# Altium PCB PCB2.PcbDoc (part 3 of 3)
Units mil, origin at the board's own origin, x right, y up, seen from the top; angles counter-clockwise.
Board outline 10275.59 x 4173.23 mil, 2 copper layers (Top Layer, Bottom Layer); 158 components, 159 nets, 776 pads, 338 vias.
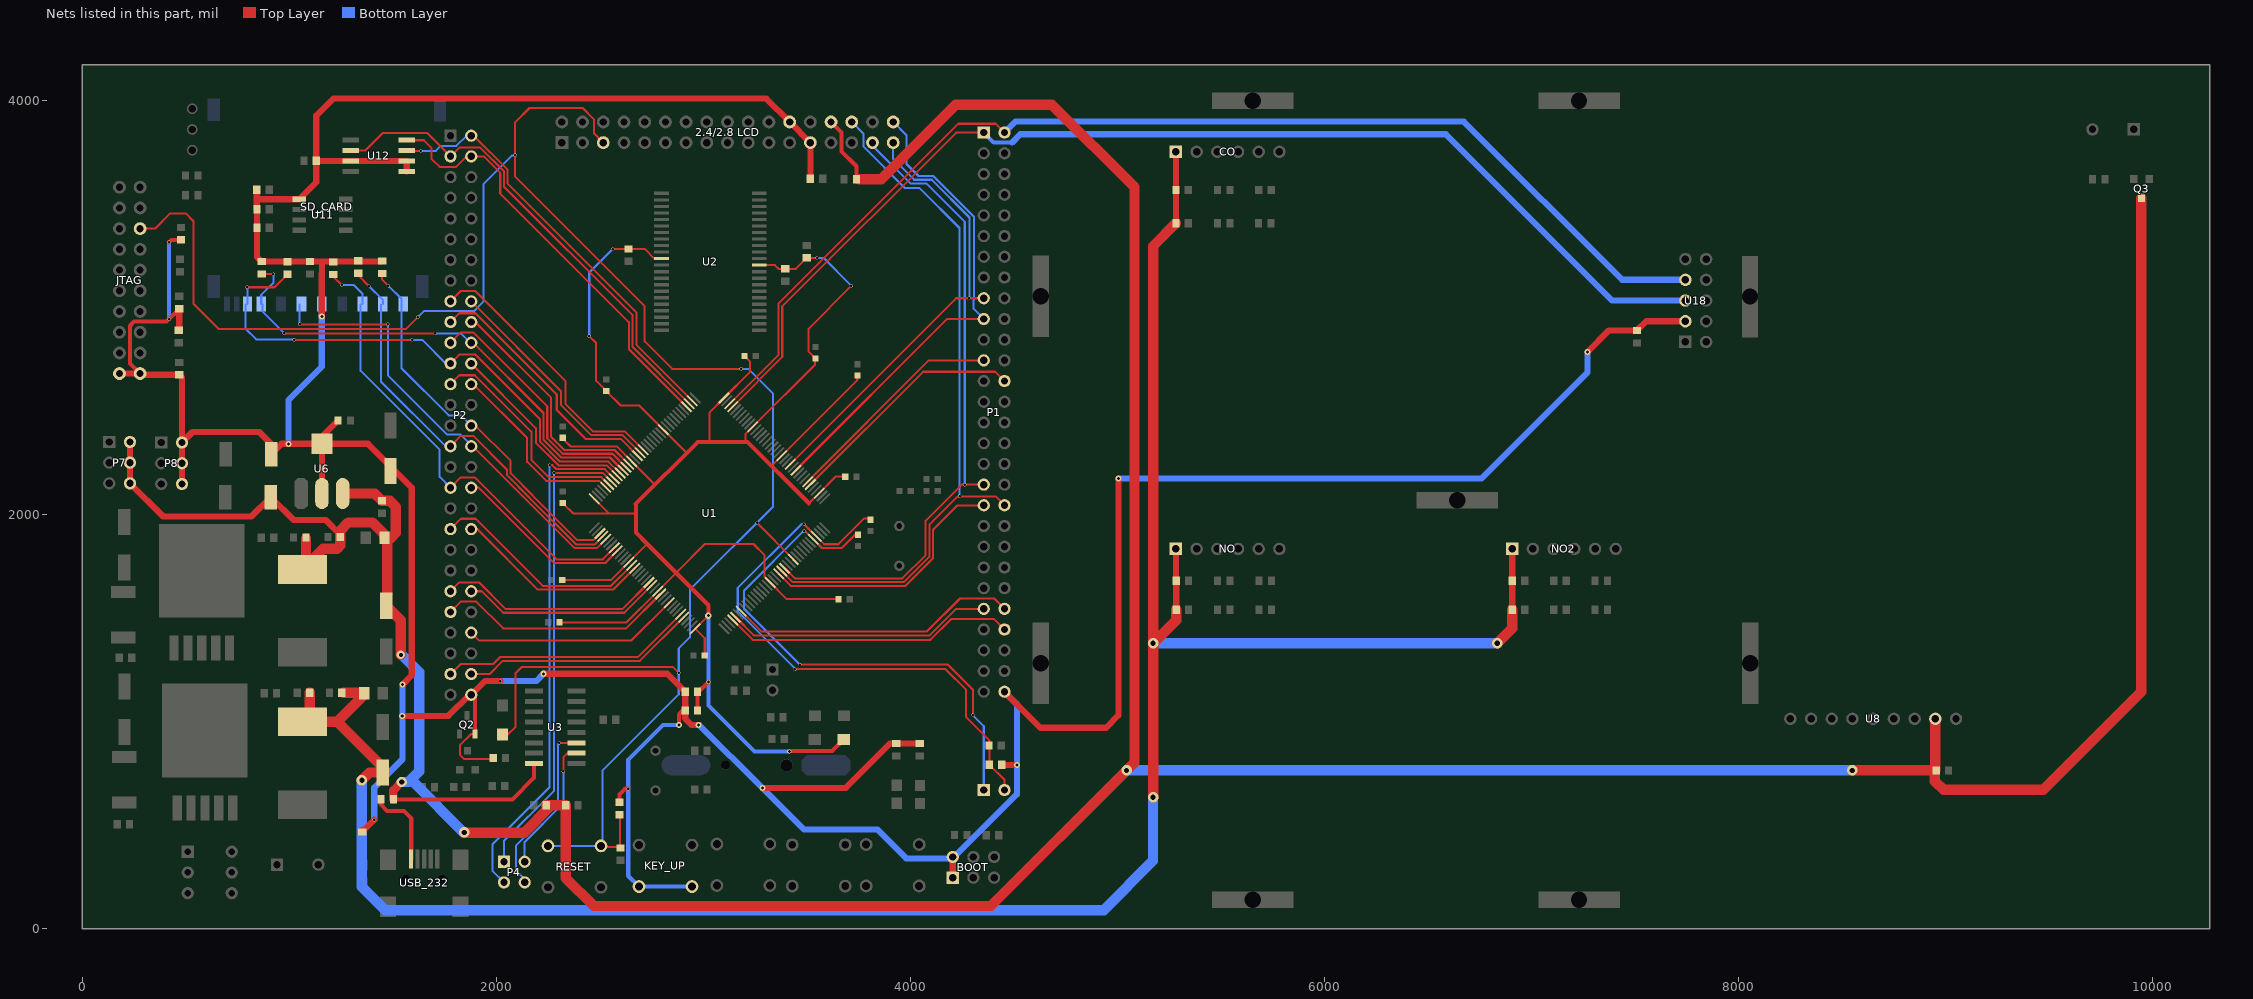
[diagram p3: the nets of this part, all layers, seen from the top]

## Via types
v1: diameter 16, hole 12, Top Layer to Bottom Layer, 183 vias
v2: diameter 60, hole 36, Top Layer to Bottom Layer, 50 vias
v3: diameter 27.56, hole 27.56, Top Layer to Bottom Layer, 32 vias
v4: diameter 30, hole 15, Top Layer to Bottom Layer, 27 vias
v5: diameter 50, hole 25, Top Layer to Bottom Layer, 19 vias
v6: diameter 125.98, hole 125.98, Top Layer to Bottom Layer, 16 vias
v7: diameter 20, hole 15, Top Layer to Bottom Layer, 4 vias
v8: diameter 196.85, hole 118.11, Top Layer to Bottom Layer, 4 vias
v9: diameter 30, hole 20, Top Layer to Bottom Layer, 1 vias
v10: diameter 40, hole 20, Top Layer to Bottom Layer, 1 vias
v11: diameter 50, hole 28, Top Layer to Bottom Layer, 1 vias

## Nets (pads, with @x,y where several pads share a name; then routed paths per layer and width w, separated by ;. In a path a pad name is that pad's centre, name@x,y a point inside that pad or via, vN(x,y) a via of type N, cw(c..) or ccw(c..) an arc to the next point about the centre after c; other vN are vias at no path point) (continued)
PA6: P1.26 U1.42 | length 1181.3
  Top Layer w10: U1.42@3517.19,2145.31 4061.48,2689.61 4409.37,2689.61 P1.26@4454.37,2644.61
PA7: P1.23 U1.43 | length 1093.6
  Top Layer w10: U1.43@3503.27,2159.23 4088.64,2744.61 P1.23@4354.37,2744.61
PA8: P2.24 U1.100 | length 971.4
  Top Layer w10: P2.24@1879.37,2729.61 2191.37,2417.61 2191.37,2346.83 2300.6,2237.61 2534.05,2237.61 U1.100@2584.59,2187.07
PA9: P4.3 U1.101 | length 2493.3
  Top Layer w10: v1(2257.37,2238.61) 2271.37,2238.61 2287.37,2222.61 2288.07,2222.61 2291.07,2219.61 2524.17,2219.61 U1.101@2570.9,2172.88
  Bottom Layer w10: P4.3@2037.37,223.61 1981.37,279.61 1981.37,406.61 2257.37,682.61 v1(2257.37,2238.61)
PA10: P4.1 U1.102 | length 2273.5
  Top Layer w10: v1(2279.37,2201.61) 2514.34,2201.61 U1.102@2556.98,2158.96
  Bottom Layer w10: P4.1@2037.37,323.61 2037.37,424.61 2279.37,666.61 v1(2279.37,2201.61)
PA11: P2.25 U1.103 | length 1079.4
  Top Layer w10: P2.25@1779.37,2629.61 1822.37,2672.61 1896.51,2672.61 2169.37,2399.75 2169.37,2264.61 2253.37,2180.61 2459.22,2180.61 2459.49,2180.87 2507.23,2180.87 U1.103@2543.06,2145.04
PA12: P2.26 U1.104 | length 923.8
  Top Layer w10: P2.26@1879.37,2629.61 1882.37,2626.61 1892.37,2626.61 2149.37,2369.61 2149.37,2254.61 2241.37,2162.61 2466.68,2162.61 2466.94,2162.87 2497.39,2162.87 U1.104@2529.14,2131.12
PB1: "2.4/2.8 LCD.34" P1.19 U1.47 | length 2384.3
  Top Layer w10: U1.47@3447.59,2214.91 4177.29,2944.61 P1.19@4354.37,2944.61
  Bottom Layer w10: 3917,3896 3981,3832 3981,3692.98 4039.37,3634.61 4110.83,3634.61 4306.37,3439.06 4306.37,3035.91 4305.37,3034.91 4305.37,2993.61 P1.19@4354.37,2944.61
PB5: P2.50 U1.135 | length 1046.5
  Top Layer w10: P2.50@1879.37,1429.61 1916.37,1392.61 2653.13,1392.61 U1.135@2835.14,1574.61
PB8: P2.53 U1.139 | length 1231.3
  Top Layer w10: P2.53@1779.37,1229.61 1827.37,1277.61 1984.37,1277.61 2018.37,1311.61 2683.48,1311.61 U1.139@2890.81,1518.94
PB9: P2.54 U1.140 | length 1139.4
  Top Layer w10: P2.54@1879.37,1229.61 1967.37,1229.61 2031.37,1293.61 2693.32,1293.61 U1.140@2904.73,1505.02
PB10: P1.1 U1.69 U18.5 | length 5661.6
  Top Layer w10: U1.69@3141.36,2521.13 3381.37,2761.14 3381.37,3005 4220.98,3844.61 P1.1@4354.37,3844.61
  Bottom Layer w10: 4530.91,3836.61 4534.91,3836.61
  Bottom Layer w20: P1.1@4354.37,3844.61 4402.37,3796.61 4490.91,3796.61
  Bottom Layer w30: 4490.91,3796.61 4530.91,3836.61 ; 4534.91,3836.61 6585.91,3836.61 7389.06,3033.46 U18.5@7742.78,3033.46
PB11: P1.2 U1.70 U18.7 | length 5676.5
  Top Layer w10: U1.70@3127.44,2535.05 3362.37,2769.98 3362.37,3017.61 4231.9,3887.13 4411.84,3887.13 P1.2@4454.37,3844.61
  Bottom Layer w30: P1.2@4454.37,3844.61 4507.37,3897.61 6672.91,3897.61 7437.06,3133.46 U18.7@7742.78,3133.46
PB13: P2.2 U1.74 U12.7 | length 2046.1
  Top Layer w10: U12.7@1570.37,3755.61 v1(1635.37,3755.61) ; P2.2@1879.37,3829.61 1890.28,3829.61 2055.37,3664.52 2055.37,3597.61 2676.37,2976.61 2676.37,2819.06 U1.74@2946.72,2548.7
  Bottom Layer w10: v1@1635.37,3756.61 1708.37,3756.61 1732.37,3780.61 1807.81,3780.61 P2.2@1856.81,3829.61
PB14: P2.3 U1.75 U12.2 | length 2379.5
  Top Layer w10: U12.2@1298.37,3757.54 1366.31,3757.54 1451.37,3842.61 1666.37,3842.61 P2.3@1779.37,3729.61 1821.9,3772.13 1922.3,3772.13 2037.37,3657.06 2037.37,3582.89 2658.37,2961.89 2658.37,2809.22 U1.75@2932.8,2534.78
PB15: P2.4 U1.76 U12.8 | length 2091.1
  Top Layer w10: U12.8@1568.37,3807.61 1650.37,3807.61 1688.37,3769.61 1688.37,3716.61 1726.37,3678.61 1806.37,3678.61 1857.37,3729.61 P2.4@1879.37,3729.61 1939.37,3729.61 2019.37,3649.61 2019.37,3549.61 2640.37,2928.61 2640.37,2799.38 U1.76@2918.89,2520.87
PC6: P2.20 U1.96 | length 1156.1
  Top Layer w10: P2.20@1879.37,2929.61 1899.37,2929.61 2265.37,2563.61 2265.37,2374.66 2328.42,2311.61 2571.4,2311.61 U1.96@2640.26,2242.74
PC7: P2.21 U1.97 | length 1227.8
  Top Layer w10: P2.21@1779.37,2829.61 1829.37,2879.61 1889.51,2879.61 2246.37,2522.75 2246.37,2368.2 2320.97,2293.61 2561.56,2293.61 U1.97@2626.34,2228.83
PC8: P2.22 R21.2 SD_CARD.7 U1.98 | length 2391.1
  Top Layer w10: R21.2@867.37,3161.61 v1@923.37,3161.61 ; v1(976.8,2874.61) v1(1706.37,2874.61) ; P2.22@1879.37,2829.61 1889.37,2829.61 2228.37,2490.61 2228.37,2360.75 2313.51,2275.61 2549.34,2275.61 2610.04,2214.91 U1.98@2612.42,2214.91
  Bottom Layer w10: SD_CARD.7@865.44,3016.97 865.44,3060.68 924.37,3119.61 v1(924.37,3160.61) ; SD_CARD.7@870.37,3013.61 870.37,2981.04 v1(976.8,2874.61) ; v1@1707.37,2874.61 1829.37,2874.61 1874.37,2829.61 P2.22@1879.37,2829.61
PC9: P2.23 R22.2 SD_CARD.8 U1.99 | length 2616
  Top Layer w10: v1(798.37,3097.61) 929.37,3097.61 R22.2@992.37,3160.61 ; v1(1025.37,2843.61) v1(1593.37,2843.61) ; P2.23@1779.37,2729.61 1821.9,2772.13 1899.84,2772.13 2210.37,2461.61 2210.37,2353.29 2308.05,2255.61 2541.5,2255.61 2596.12,2200.99 U1.99@2598.51,2200.99
  Bottom Layer w10: SD_CARD.8@789.37,3014.61 789.37,2896.61 840.37,2845.61 v1@1023.37,2845.61 ; SD_CARD.8@798.37,3016.61 v1(798.37,3097.61) ; v1@1022.72,2846.26 v1@1023.37,2845.61 ; v1(1025.37,2843.61) v1@1023.37,2845.61 ; v1(1593.37,2843.61) 1642.37,2843.61 1756.37,2729.61 P2.23@1779.37,2729.61
PC10: P2.30 R18.1 SD_CARD.9 U1.111 | length 1848.4
  Top Layer w10: R18.1@1449.37,3164.61 1449.37,3134.61 v1(1479.37,3104.61) ; P2.30@1879.37,2429.61 1899.37,2429.61 2069.37,2259.61 2069.37,2198.69 2178.37,2089.69 2178.37,2089 2390.71,1876.66 2469.05,1876.66 U1.111@2501.07,1908.68
  Bottom Layer w10: v1(1479.37,3104.61) 1542.46,3041.51 1542.46,2706.37 1770.23,2478.61 1830.37,2478.61 P2.30@1879.37,2429.61
PC11: P2.31 R23.2 SD_CARD.1 U1.112 | length 2032.1
  Top Layer w10: R23.2@1333.37,3155.61 v1(1385.37,3103.61) ; P2.31@1779.37,2329.61 1829.37,2379.61 1889.51,2379.61 2051.37,2217.75 2051.37,2191.24 2160.37,2082.24 2160.37,2081.54 2386.3,1855.61 2475.84,1855.61 U1.112@2514.99,1894.76
  Bottom Layer w10: v1(1385.37,3103.61) 1452.37,3036.61 SD_CARD.1@1452.37,3016.61 ; SD_CARD.1@1443.37,3014.61 1443.37,2641.61 1755.37,2329.61 P2.31@1779.37,2329.61
PC12: P2.32 SD_CARD.5 U1.113 | length 2184.1
  Top Layer w10: v1(1050.34,2918.61) v1@1477.37,2918.61 ; P2.32@1879.37,2329.61 1887.55,2329.61 2142.37,2074.78 2142.37,2074.08 2378.85,1837.61 2485.67,1837.61 U1.113@2528.91,1880.84
  Bottom Layer w10: v1(1050.34,2918.61) SD_CARD.5@1050.34,3014.97 ; v1(1476.37,2918.61) 1476.37,2672.46 1761.75,2387.08 1826.9,2387.08 P2.32@1879.37,2334.61
PC13: P1.48 U1.7 | length 1398.1
  Top Layer w10: U1.7@3183.12,1532.86 3280.37,1435.61 4080.37,1435.61 4239.37,1594.61 4404.37,1594.61 P1.48@4454.37,1544.61
PD2: P2.35 R20.2 SD_CARD.2 U1.116 | length 2299.7
  Top Layer w10: R20.2@1213.37,3159.61 1213.37,3148.61 v1(1253.37,3108.61) ; P2.35@1779.37,2129.61 1829.37,2179.61 1896.37,2179.61 2292.37,1783.61 2515.19,1783.61 U1.116@2570.67,1839.08
  Bottom Layer w10: v1(1253.37,3108.61) 1312.37,3108.61 1354.37,3066.61 SD_CARD.2@1354.37,3016.61 ; SD_CARD.2@1345.37,3014.61 1345.37,2693.61 1726.37,2312.61 1726.37,2182.61 P2.35@1779.37,2129.61
PD3: P2.36 U1.117 | length 880.7
  Top Layer w10: P2.36@1879.37,2129.61 1915.37,2129.61 2279.37,1765.61 2525.03,1765.61 U1.117@2584.59,1825.16
PD6: P2.39 U1.122 | length 1071.2
  Top Layer w10: P2.39@1779.37,1929.61 1829.37,1979.61 1900.37,1979.61 2224.43,1655.54 2554.16,1655.54 U1.122@2654.18,1755.57
PD7: P2.40 U1.123 | length 952.8
  Top Layer w10: P2.40@1879.37,1929.61 1909.37,1929.61 2201.43,1637.54 2564,1637.54 U1.123@2668.1,1741.65
PE5: P1.50 U1.4 | length 1415.1
  Top Layer w10: U1.4@3141.36,1491.1 3237.85,1394.61 4096.37,1394.61 4196.37,1494.61 4404.37,1494.61 P1.50@4454.37,1444.61
PE6: P1.47 U1.5 | length 1288.7
  Top Layer w10: U1.5@3155.28,1505.02 3243.69,1416.61 4092.91,1416.61 4220.91,1544.61 P1.47@4354.37,1544.61
PF8: P1.37 U1.20 | length 1256.4
  Top Layer w10: U1.20@3364.07,1713.81 3422.27,1655.61 3706.51,1655.61 3706.57,1655.67 3777.17,1655.67 3777.23,1655.61 3976.28,1655.61 4109.37,1788.69 4109.37,1926.61 4227.37,2044.61 P1.37@4354.37,2044.61
PF9: "2.4/2.8 LCD.30" P1.38 U1.21 | length 3443.7
  Top Layer w10: U1.21@3377.99,1727.73 3432.11,1673.61 3699.05,1673.61 3699.12,1673.67 3784.62,1673.67 3784.69,1673.61 3968.83,1673.61 4091.37,1796.15 4091.37,1950.61 4228.37,2087.61 4411.37,2087.61 P1.38@4454.37,2044.61
  Bottom Layer w10: 3717,3896 3773,3840 3773,3777.78 3974.17,3576.61 4044.37,3576.61 4237.37,3383.61 v1(4237.37,2087.61)
PF10: "2.4/2.8 LCD.31" P1.35 U1.22 | length 3149.9
  Top Layer w10: U1.22@3391.91,1741.65 3441.95,1691.61 3691.6,1691.61 3691.66,1691.67 3792.08,1691.67 3792.14,1691.61 3961.37,1691.61 4073.37,1803.61 4073.37,1970.61 4247.37,2144.61 P1.35@4354.37,2144.61
  Bottom Layer w10: 3817,3796 3817,3781.61 4001,3597.61 4078.37,3597.61 4262.37,3413.61 v1(4262.37,2144.61)
PF11: "2.4/2.8 LCD.33" P1.17 U1.49 | length 2219.7
  Top Layer w10: U1.49@3419.75,2242.74 4221.61,3044.61 P1.17@4354.37,3044.61
  Bottom Layer w10: 3917,3796 3917,3717.61 4018,3616.61 4103.37,3616.61 4285.37,3434.61 v1(4285.37,3045.61)
PG6: P2.17 U1.91 | length 1334.1
  Top Layer w10: P2.17@1779.37,3029.61 1829.37,3079.61 1899.37,3079.61 2335.37,2643.61 2335.37,2533.06 2466.83,2401.61 2620.56,2401.61 U1.91@2710.09,2312.07
PG7: P2.18 U1.92 | length 1158.1
  Top Layer w10: P2.18@1879.37,3029.61 2312.37,2596.61 2312.37,2530.61 2459.37,2383.61 2610.76,2383.61 U1.92@2695.94,2298.42
PG8: P2.19 U1.93 | length 1249.4
  Top Layer w10: P2.19@1779.37,2929.61 1821.9,2972.13 1899.84,2972.13 2292.37,2579.61 2292.37,2504.61 2431.37,2365.61 2600.89,2365.61 U1.93@2682.26,2284.24
PG13: P2.45 U1.128 | length 1082.4
  Top Layer w10: P2.45@1779.37,1629.61 1821.9,1672.13 1916.84,1672.13 2045.37,1543.61 2609.26,1543.61 U1.128@2737.7,1672.05
PG14: P2.46 U1.129 | length 970.2
  Top Layer w10: P2.46@1879.37,1629.61 1929.37,1629.61 2033.37,1525.61 2619.09,1525.61 U1.129@2751.62,1658.13
PG15: P2.47 U1.132 | length 1156.8
  Top Layer w10: P2.47@1779.37,1529.61 1829.37,1579.61 1904.37,1579.61 2033.37,1450.61 2627.61,1450.61 U1.132@2793.38,1616.37
RESET: "2.4/2.8 LCD.5" C12.2 D3.1 JTAG.15 R3.1 RESET.1 U1.25 | length 10024.3
  Top Layer w10: JTAG.15@280.37,3380.61 352.37,3380.61 426.37,3454.61 500.37,3454.61 538.37,3416.61 538.37,3018.61 661.37,2895.61 1563.37,2895.61 v1(1620.37,2952.61) ; D3.1@2030.37,937.61 2056.37,937.61 2092.37,973.61 2092.37,1232.61 2124.37,1264.61 2853.37,1264.61 v1(2881.37,1236.61) ; RESET.1@2512.28,414.61 2532.28,394.61 2597.37,394.61 2597.37,548.61 R3.1@2595.37,550.61 ; 2517,3796 2473,3840 2473,3907 2417,3963 2160.76,3963 2091.37,3893.61 v1(2091.37,3734.61) 2091.37,3631.61 2716.37,3006.61 2716.37,2836.61 2849.37,2703.61 v1(3183.37,2703.61) ; v1(3259.37,1959.61) U1.25@3433.67,1783.4
  Bottom Layer w10: v1(1620.37,2952.61) 1650.37,2982.61 1892.51,2982.61 1939.37,3029.46 1939.37,3596.61 2077.37,3734.61 v1(2091.37,3734.61) ; RESET.1@2256.37,412.61 2268.98,400 2512.28,400 2512.28,762.51 2881.37,1131.61 2881.37,1353.61 2935.37,1407.61 2935.37,1636.61 3337.37,2038.61 3337.37,2582.61 3216.37,2703.61 v1(3183.37,2703.61)
RXD: P4.4 U3.3 | length 861.2
  Top Layer w10: v1(2305.37,897.61) U3.3@2387.73,897.61
  Bottom Layer w10: P4.4@2137.37,223.61 2137.37,238.55 2094.84,281.08 2094.84,401.53 2298.37,605.06 2298.37,890.61 v1(2305.37,897.61)
TXD: P4.2 U3.2 | length 655.7
  Top Layer w10: v1(2324.37,759.61) 2324.37,828.61 2343.37,847.61 U3.2@2387.73,847.61
  Bottom Layer w10: P4.2@2137.37,323.61 2137.37,418.61 2324.37,605.61 v1@2324.37,761.61
VCC3.3: "2.4/2.8 LCD.24" "2.4/2.8 LCD.25" BOOT.1 BOOT.2 C3.1 C30.2 C32.1 C33.1 C34.2 C49.1 C50.1 D7.2 JTAG.1 JTAG.2 KEY_UP.1 P1.56 P2.56 P8.2 P8.4 P8.6 Q2.2 R3.2 R4.2 R5.1 R6.1 R7.1 R8.1 R9.1 R10.1 R18.2 R19.1 R20.1 R21.1 R22.1 R23.1 R24.1 R25.1 R26.1 R28.1 R29.1 SD_CARD.4 U6.2 U6.4 U11.5 U12.3 U12.5 U12.6 U18.3 | length 23111
  Top Layer w10: Q2.2@1896.77,940.31 1879.08,940.31 1824.37,885.61 1824.37,840.61 1846.37,818.61 R19.1@1985.37,818.61
  Top Layer w20: JTAG.1@280.37,2680.61 231.37,2729.61 231.37,2911.61 251.37,2931.61 407.37,2931.61 R7.1@469.37,2993.61 ; v1(420.37,3314.61) 432.37,3326.61 R10.1@477.37,3326.61 ; P2.56@1879.37,1129.61 1896.77,1112.2 Q2.2@1896.77,940.31 ; R3.2@2595.37,610.61 2595.37,648.61 2623.37,676.61 v1(2637.37,676.61) ; v4(2882.37,983.61) 2882.37,1035.74 R9.1@2903.8,1057.17
  Top Layer w30: JTAG.2@180.37,2680.61 JTAG.1@280.37,2680.61 ; JTAG.1@286.37,2674.61 R5.1@469.37,2674.61 482.37,2661.61 P8.2@482.37,2347.61 ; R6.1@469.37,2892.61 R7.1@469.37,2993.61 ; P8.6@482.37,2147.61 P8.4@482.37,2247.61 P8.2@482.37,2347.61 ; C32.1@843.37,3568.61 843.37,3475.61 R28.1@844.37,3474.61 ; R22.1@991.37,3221.61 R21.1@867.37,3221.61 844.37,3244.61 R29.1@844.37,3384.61 R28.1@844.37,3474.61 ; R22.1@992.37,3221.61 C30.2@1100.37,3221.61 1446.37,3221.61 R18.2@1449.37,3224.61 ; U6.4@1121.31,2339.54 C49.1@1236.37,2454.61 ; C33.1@1132.37,3707.61 U12.6@1568.37,3707.61 U12.5@1568.37,3657.61 ; v4(1157.76,2957) 1157.76,3164 1158.37,3164.61 1158.37,3219.61 ; U6.2@1158.4,2101.54 U6.4@1158.4,2341.54 ; R26.1@1352.37,475.61 R26.1@1352.37,467.61 v1(1411.37,526.61) ; v4(1546.37,1027.74) 1769.37,1027.74 1871.24,1129.61 P2.56@1879.37,1129.61 1945.37,1195.61 v1(2020.37,1195.61) ; v4(1547.37,1178.61) 1592.37,1223.61 1592.37,2129.61 1380.43,2341.54 U6.4@1158.4,2341.54 ; v4(2228.24,1230.74) 2826.24,1230.74 R8.1@2912.37,1144.61 R9.1@2912.37,1065.74 ; R9.1@2912.37,1053.61 2912.37,1014.74 2943.5,983.61 v4(2977.37,983.61) ; v4(3285.37,679.61) 3687.37,679.61 3902.37,894.61 R24.1@3932.37,894.61 R25.1@4045.37,894.61 ; 3517,3796 3417,3896 3304,4009 1213.76,4009 1131.37,3926.61 C33.1@1131.37,3708.61 1131.37,3605.02 U11.5@1048.96,3522.61 844.37,3522.61 R28.1@844.37,3474.61 ; C3.1@3517.37,3619.61 3517.37,3802 ; BOOT.1@4204.37,239.61 BOOT.2@4204.37,339.61 ; R4.2@4442.24,790.74 v4(4514.37,790.74) ; P1.56@4454.37,1144.61 4628.24,970.74 4945.05,970.74 5004.37,1030.06 v4(5004.37,2174.74) ; v4(7269.37,2784.61) 7373.5,2888.74 C34.2@7508.37,2888.74 7553.09,2933.46 U18.3@7742.78,2933.46 ; P8.2@482.37,2347.61 533.37,2398.61 855.37,2398.61 913.37,2340.61 D7.2@913.37,2291.61 963.31,2341.54 U6.4@1158.4,2341.54
  Bottom Layer w20: v1(420.37,2943.61) v1(420.37,3314.61) ; v4(2882.37,983.61) 2805.37,983.61 2637.37,815.61 v1(2637.37,676.61) 2637.37,255.7 KEY_UP.1@2689.46,203.61 KEY_UP.1@2945.37,203.61
  Bottom Layer w30: v4(997.37,2340.61) 997.37,2553.61 1157.76,2714 v4(1157.76,2957) SD_CARD.4@1157.76,3016.97 ; v1(1411.37,526.61) 1411.37,681.74 1547.37,817.74 1547.37,1026.74 v4(1546.37,1027.74) ; v4@1547.37,1027.74 v4(1547.37,1178.61) ; v1(2020.37,1195.61) 2193.1,1195.61 v4(2228.24,1230.74) ; v4(2977.37,983.61) 2981.37,983.61 v4(3285.37,679.61) 3486.37,478.61 3841.37,478.61 3980.37,339.61 4204.37,339.61 4514.37,649.61 v4(4514.37,790.74) 4514.37,1084.61 P1.56@4454.37,1144.61 ; v4(5004.37,2174.74) 6758.37,2174.74 7269.37,2685.74 v4(7269.37,2784.61)
VCC3.3M: C1.1 C2.1 C13.2 C14.2 C15.2 C16.2 C17.2 C18.2 C19.2 C20.2 C21.2 C22.2 C23.2 D2.1 R1.2 R8.2 R9.2 U1.17 U1.39 U1.52 U1.62 U1.72 U1.84 U1.95 U1.108 U1.121 U1.131 U1.144 U2.11 U2.33 | length 10933.6
  Top Layer w10: C14.2@2305.87,1479.54 2629.21,1479.54 U1.131@2779.69,1630.02 2868.56,1718.9 3007.27,1857.61 3242.37,1857.61 3294.88,1805.1 3294.88,1699.45 U1.17@3322.55,1671.78 3402.66,1591.67 C23.2@3661.37,1591.67 ; C17.2@2319.31,2369.11 2358.81,2329.61 2581.21,2329.61 U1.95@2654.42,2256.4 2764.21,2146.61 ; C16.2@2321.31,2055.11 2370.81,2005.61 2543.3,2005.61 ; C15.2@2331.81,1684.61 2555.89,1684.61 U1.121@2640.5,1769.22 2729.37,1858.09 2729.37,1858.61 ; v1(2449.37,2861.61) 2482.37,2828.61 2482.37,2646.04 C18.2@2531.31,2597.11 ; U1.108@2473.46,2075.44 2543.3,2005.61 ; C18.2@2529.31,2598.67 2600.37,2527.61 2689.43,2527.61 U1.84@2807.53,2409.51 2918.93,2298.11 ; v1(2562.87,3282.11) 2563.37,3282.61 2717.37,3282.61 2763.94,3236.04 U2.33@2798.28,3236.04 ; 2674.37,2005.61 2543.3,2005.61 ; C13.2@3006.87,1319.54 3006.87,1402.85 U1.144@2960.64,1449.07 v4@3025.37,1513.8 ; 3030.37,2350.61 3030.37,2493.16 U1.72@3099.84,2562.62 3226.37,2689.16 3226.37,2738.17 C19.2@3198.87,2765.67 ; 3203.37,2350.61 3203.37,2387.77 U1.62@3239.03,2423.43 3540.37,2724.77 C20.2@3540.37,2752.11 ; U2.11@3270.72,3204.54 3345.43,3204.54 3363.37,3186.61 R1.2@3395.37,3186.61 3446.37,3186.61 C2.1@3499.37,3239.61 v1@3549.37,3239.61 ; 3329.8,2236.04 3330.03,2236.04 U1.52@3378.23,2284.24 3743.37,2649.38 C21.2@3743.37,2674.61 ; 3510.37,2054.48 U1.39@3559.18,2103.28 3639.56,2183.67 C22.2@3690.87,2183.67 ; C20.2@3541.31,2754.11 3508.37,2787.04 3508.37,2897.61 v1(3715.37,3104.61)
  Top Layer w20: 2673.37,2050.61 2973.37,2350.61 3030.37,2350.61 3203.37,2350.61 3214.24,2350.61 3510.37,2054.48 ; 2674.37,2049.61 2674.37,2005.61 2674.37,1913.61 2729.37,1858.61 ; 2729.37,1858.09 2868.56,1718.9 3025.37,1562.09 v4@3025.37,1513.8 ; R9.2@2972.37,1053.61 2972.37,1139.61 v7(3024.37,1191.61) ; v7@3417.37,857.61 3622.37,857.61 D2.1@3678.37,913.61
  Bottom Layer w10: v1(2449.37,2861.61) 2449.37,3168.61 v1(2562.87,3282.11) ; v1@3552.37,3239.61 3580.37,3239.61 v1(3715.37,3104.61)
  Bottom Layer w20: v4(3024.37,1511.61) 3024.37,1077.61 3246.37,855.61 v7(3415.37,855.61)
  other v1: 3549.37,3240.61
VCC5: "2.4/2.8 LCD.28" C4.1 C28.2 C29.2 C47.1 C48.1 C51.1 C52.1 C54.2 D6.2 F1.2 L1.2 P7.2 P7.4 P7.6 Q3.3 R43.2 U3.16 U6.3 U8.2 | length 21617.6
  Top Layer w20: F1.2@1503.37,624.61 2078.37,624.61 2183.01,729.24 U3.16@2183.01,797.61 ; 3617,3896 3668,3845 3668,3753.37 3739.37,3682 ; C4.1@3739.37,3619.61 3739.37,3678.63
  Top Layer w30: P7.2@231.37,2350.61 P7.4@231.37,2250.61 P7.6@231.37,2150.61 391.37,1990.61 817.37,1990.61 D6.2@911.37,2084.61 1022.37,1973.61 1176.37,1973.61 C48.1@1247.37,1902.61
  Top Layer w40: F1.2@1503.37,624.61 1503.37,668.61 v5(1543.37,708.61)
  Top Layer w50: L1.2@1064.37,1734.61 1165.37,1835.61 1231.24,1835.61 1247.37,1851.74 C48.1@1247.37,1891.61 C48.1@1247.37,1902.61 ; L1.2@1081.37,1732.61 R43.2@1081.37,1883.61 ; 1247.37,1922.61 1286.5,1961.74 1401.37,1961.74 1473.37,1889.74 C47.1@1473.37,1616.61 ; U6.3@1258.4,2101.54 1413.43,2101.54 C51.1@1448.37,2066.61 1485.5,2066.61 1515.37,2036.74 1515.37,1911.74 1492.24,1888.61 C54.2@1460.24,1888.61 ; C47.1@1469.37,1559.61 1539.37,1489.61 v10(1539.37,1322.61) ; v5@1846.37,463.74 2134.5,463.74 2261.94,591.17 ; C29.2@2241.37,595.61 C28.2@2335.37,595.61 2335.37,244.61 2470.24,109.74 4389.37,109.74 v5(5044.24,764.61) 5082.37,802.74 5082.37,3579.74 4682.5,3979.61 4219.61,3979.61 3860,3620 C4.1@3753,3620 ; v5(8548.24,764.61) 8948.37,764.61 U8.2@8948.37,1009.74 ; C52.1@8947.37,757.74 8947.37,712.74 8989.37,670.74 ; 8989.37,670.61 9471.37,670.61 9944.37,1143.61 Q3.3@9944.37,3526.61
  Bottom Layer w30: 1577.37,708.61 1599.37,708.61
  Bottom Layer w50: v10@1541.44,1324.67 1628.37,1237.74 1628.37,759.61 1577.37,708.61 v5(1543.37,708.61) ; 1599.37,708.61 v5@1844.24,463.74 ; v5(5044.24,764.61) v5(8548.24,764.61)
  other v5: 1846,465
VCC6: C35.1 C36.1 C37.1 C38.1 C39.1 C40.1 C43.1 C44.1 C53.2 CO.1 L2.2 NO2.1 NO.1 R45.2 | length 11583.1
  Top Layer w30: C53.2@1359.37,1127.61 C53.2@1359.37,1139.61 ; C43.1@1452.37,754.61 C43.1@1452.37,778.61 ; NO.1@5282.2,1833.84 5282.2,1681.91 C38.1@5283.37,1680.74 C37.1@5283.37,1540.74 ; C35.1@5282.2,3566.91 CO.1@5282.2,3751.84 ; C36.1@5282.37,3406.74 C35.1@5282.37,3566.74 ; C39.1@6906.17,1680.74 NO2.1@6906.17,1833.84 ; C40.1@6906.37,1540.74 C39.1@6906.37,1680.54
  Top Layer w50: L2.2@1064.37,999.61 1231.37,999.61 ; L2.2@1099.37,1062.61 R45.2@1099.37,1139.61 ; C44.1@1263.37,1139.61 C53.2@1359.37,1139.61 ; v5(1351.37,716.61) 1389.37,754.61 C43.1@1452.37,754.61 ; C53.2@1359.37,1127.61 1231.37,999.61 ; C43.1@1452.37,778.61 1231.37,999.61 ; v5(5172.37,634.74) v5(5172.37,1378.74) ; C36.1@5282.37,3406.74 5172.37,3296.74 v5(5172.37,1378.74) ; C37.1@5283.37,1540.74 5283.37,1489.74 v5(5172.37,1378.74) ; v5(6834.37,1378.74) 6906.37,1450.74 C40.1@6906.37,1540.74
  Bottom Layer w50: v5(1351.37,716.61) 1351.37,201.61 1463.37,89.61 4933.24,89.61 5171.37,327.74 v5@5171.37,633.74 ; v5(5172.37,1378.74) v5(6834.37,1378.74)
VDDA: C10.2 C11.2 P5.2 R4.1 U1.33 | length 2794
  Top Layer w10: v1(3442.37,1253.61) 4169.37,1253.61 4269.37,1153.61 4269.37,1021.61 4381.37,909.61 R4.1@4381.37,791.61 4454.37,718.61 P5.2@4454.37,669.61 ; v1(3486.18,1953.61) 3583.18,1856.61 3651.55,1856.61 3775.05,1980.11 C11.2@3803.43,1980.11
  Bottom Layer w10: v1@3446.37,1252.61 3166.37,1532.61 3166.37,1645.61 3474.37,1953.61 v1(3486.18,1953.61)
VREF+: C24.2 P5.1 U1.32 | length 2595.4
  Top Layer w10: v1(3466.37,1275.61) 4180.37,1275.61 4302.37,1153.61 v1@4302.37,1031.61 ; v1@3489.96,1919.61 3492.31,1919.61 U1.32@3531.34,1880.57 ; U1.32@3531.11,1880.84 3573.34,1838.61 3669.37,1838.61 3734.87,1904.11 C24.2@3747.43,1904.11
  Bottom Layer w10: v1(3466.37,1275.61) 3196.37,1545.61 3196.37,1632.61 3487.37,1923.61 v1(3487.37,1919.61) ; v1(4301.37,1031.61) 4354.37,978.61 P5.1@4354.37,669.61
VUSB: F1.1 USB_232.1 | length 404.2
  Top Layer w20: F1.1@1440.37,627.74 1440.37,601.61 1473.37,568.61 1554.37,568.61 1589.37,533.61 USB_232.1@1589.37,332.74
pads on no net: "2.4/2.8 LCD.32" BT1.0 JTAG.11 JTAG.17 JTAG.19 SD_CARD.10 SD_CARD.11 SD_CARD.12 U1.106 U3.9 U3.10 U3.11 U3.12 U3.15 U8.5 U8.6 U8.7 U8.8 U8.9 U17.1 U17.6 U18.2 U18.4 U18.6 U18.8 U18.9 U18.10 USB_232.4 USB_232.6 USB_232.7 USB_232.8 USB_232.9 USB_232.MH1 USB_232.MH2
copper on no net:
  other v1: 9126.91,3681.61
  other v3: 10125.59,60 150,70 10069.02,83.43 10182.16,83.43 93.43,93.43 206.57,93.43 10045.59,140 10205.59,140 70,150 230,150 10069.02,196.57 10182.16,196.57 93.43,206.57 206.57,206.57 10125.59,220 150,230 10125.59,3943.23 150,3953.23 10069.02,3966.66 10182.16,3966.66 93.43,3976.66 206.57,3976.66 10045.59,4023.23 10205.59,4023.23 70,4033.23 230,4033.23 10069.02,4079.8 10182.16,4079.8 93.43,4089.8 206.57,4089.8 10125.59,4103.23 150,4113.23
  other v6: 6158.18,375.61 7782.15,375.61 4902.54,377.34 6526.51,377.34 8472.87,1329.77 9417.75,1329.77 4902.54,1635.45 6158.18,1635.45 6526.51,1635.45 7782.15,1635.45 6158.18,2293.61 4902.54,2295.34 8472.87,2430.77 9417.75,2432.13 4902.54,3553.45 6158.18,3553.45
  other v8: 10125.59,140 150,150 10125.59,4023.23 150,4033.23

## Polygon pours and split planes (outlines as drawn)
GND on Bottom Layer "Top Layer-No Net" (hatched 90Degree grid 10 track 10, remove dead copper, pour order 7): -4,2449 1707,2449 1708,2448 1722,2434 1722,1 8,1 6,-1 -4,9 -4,2446

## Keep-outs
Keep-Out Layer:
  lines w3.94: 0,150 ccw(c150,150) 150,0 10125.59,0 ccw(c10125.59,150) 10275.59,150 10275.59,4023.23 ccw(c10125.59,4023.23) 10125.59,4173.23 150,4173.23 ccw(c150,4023.23) 0,4023.23 0,150

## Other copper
Top Layer:
  region net GND: 5582.2,3825 5565.93,3841.26 5556.03,3831.36 5572.3,3815.1
  region net GND: 5601.61,3848.65 5578.98,3826.02 5591,3814 5613.63,3836.63
  region net GND: 7209.73,1890.73 7184.16,1916.3 7171.43,1903.57 7197,1878
  region net GND: 7217.54,1877.54 7243,1903 7228.15,1917.85 7202.7,1892.39
  region net GND: 5616.16,3302.16 5594.95,3323.38 5568.79,3297.21 5590,3276
  region net GND: 5572.2,3277.2 5592,3297 5565.84,3323.16 5546.04,3303.36
  region net GND: 5588,1905 5566.79,1926.21 5549.11,1908.54 5570.32,1887.32
  region net GND: 5616.21,1910.79 5595,1932 5571.14,1908.14 5592.36,1886.93
  region net GND: 5571.44,1955.56 5551.64,1935.76 5567.2,1920.2 5587,1940
  region net GND: 5597,1910 5618.21,1931.21 5595.4,1954.02 5574.19,1932.81
  rectangle net VCC6: 5189,1460 5270,1479
  region net VCC6: 5182.06,1506.06 5146,1470 5216.71,1399.29 5252.77,1435.35
  region net GND: 4540.96,840.04 4581,800 4653.12,872.12 4613.08,912.17
  region net NetC41_1: 99.83,1429.83 160,1490 124.64,1525.36 64.48,1465.19
  region net NetC41_1: 159.78,1523.42 104.06,1579.14 84.91,1560 140.63,1504.28
  rectangle net VCC6: 1250,970 1290,1028.24
  region net NetC41_1: 103.27,683.27 150,730 130.58,749.42 83.85,702.69
  region net NetC41_1: 159.2,760.8 98.32,821.68 74.99,798.34 135.86,737.46
Bottom Layer:
  region net GND: 1072.57,3092.72 1037.65,3127.65 1018.28,3108.28 1053.2,3073.35

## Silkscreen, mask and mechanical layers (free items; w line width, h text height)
Top Overlay:
  lines w3.94: 4590.54,1086.61 4669.28,1086.61 ; 4590.54,4036.78 4590.54,206.61 4590.54,100.61 8015.74,100.61 8093.91,100.61 8094.48,101.17 8094.48,179.35 8094.48,4037.24 8015.1,4037.24 7976.37,4037.24 4590.91,4037.24 ; 4590.59,1478.56 4608.91,1478.56 4669.28,1478.56 ; 4591.31,3250.21 4608.91,3250.21 4667.89,3250.21 ; 4591.45,2856.51 4608.91,2856.51 4669.01,2856.51 ; 4629.37,4036.7 4629.91,4036.16 4629.91,195.61 ; 4629.91,100.61 4629.91,206.61 ; 4668.91,100.61 4669.28,100.98 4669.28,3997.98 4669.28,4017.61 4669.28,4036.61 4668.91,4036.24 ; 4669.28,179.35 8015.74,179.35 ; 4669.28,3997.61 4669.55,3997.87 7976.37,3997.87 8015.1,3997.87 8094.21,3997.87 ; 4669.49,3958.61 4669.59,3958.5 7923.37,3958.5 8015.64,3958.5 8093.58,3958.5 8094.48,3957.61 ; 4670.91,139.98 7976.74,139.98 7995.37,139.98 8015.37,139.98 ; 5417.32,3959.1 5417.91,3958.5 ; 5456.69,179.12 5456.69,114.98 5456.69,100.83 5456.91,100.61 ; 5456.69,2068.74 7916.64,2068.74 8015.74,2068.74 ; 5456.69,3958.73 5456.69,4017.61 5456.69,4037.02 ; 5850.39,101.13 5850.39,114.98 5850.39,178.82 ; 5850.39,3958.5 5850.39,4017.61 5850.39,4036.72 ; 6440.94,2029.62 6440.94,2043.74 6440.94,2107.86 ; 6834.64,2029.37 6834.64,2068.69 6834.64,2107.69 ; 7031.49,101.4 7031.49,114.98 7031.49,178.92 ; 7031.49,3958.93 7031.49,4017.61 7031.49,4036.82 ; 7424.91,100.61 7425.19,100.88 7425.19,114.98 7425.19,179.07 ; 7425.19,3960.61 7425.19,4017.61 7425.19,4036.97 ; 8015.5,2029.37 7885.37,2029.37 5456.69,2029.37 5456.69,2108.11 7885.87,2108.11 7916.37,2108.11 8015.91,2108.11 ; 8015.74,101.24 8015.74,519.61 8015.74,4037.24 ; 8015.74,1084.86 8094.23,1084.86 ; 8015.74,2856.51 8094.43,2856.51 ; 8015.74,3053.61 8015.98,3053.36 ; 8015.74,3250.21 8094.24,3250.21 ; 8015.79,1478.56 8034.91,1478.56 8094.43,1478.56 ; 8054.83,100.61 8055.11,100.89 8055.11,204.61 8055.11,4037.05
  text "PB11" at 4510,3835 h20
  text "PB10" at 4201,3834 h25
  text "PB12" at 1626,3817 h25
  text "PB13" at 1944,3817 h25
  text "VCC" at 9877,3759 h25
  text "GND" at 9675,3757 h25
  text "PE15" at 4510,3734.85 h20
  text "PE14" at 4201,3733.85 h25
  text "PB14" at 1626,3716.89 h25
  text "PB15" at 1944,3716.89 h25
  text "PE13" at 4510,3634.7 h20
  text "PE12" at 4201,3633.7 h25
  text "PD8" at 1646.83,3616.78 h25
  text "PD9" at 1944,3616.78 h25
  text "PE11" at 4510,3534.55 h20
  text "PE10" at 4201,3533.55 h25
  text "PB10" at 1626,3516.67 h25
  text "PD11" at 1944,3516.67 h25
  text "PE9" at 4510,3434.41 h20
  text "PE8" at 4221.83,3433.41 h25
  text "PB12" at 1626,3416.56 h25
  text "PD13" at 1944,3416.56 h25
  text "PE7" at 4510,3334.26 h20
  text "PG1" at 4230.16,3333.26 h25
  text "PB14" at 1626,3316.44 h25
  text "PD15" at 1944,3316.44 h25
  text "PG0" at 4510,3234.11 h20
  text "PF15" at 4201,3233.11 h25
  text "PG2" at 1646.83,3216.33 h25
  text "PG3" at 1944,3216.33 h25
  text "PF14" at 4510,3133.96 h20
  text "PF13" at 4201,3132.96 h25
  text "PG4" at 1646.83,3116.22 h25
  text "PG5" at 1944,3116.22 h25
  text "PF12" at 4510,3033.81 h20
  text "PF11" at 4209.33,3032.81 h25
  text "PG6" at 1646.83,3016.11 h25
  text "PG7" at 1944,3016.11 h25
  text "PB2" at 4510,2933.67 h20
  text "PB1" at 4230.16,2932.67 h25
  text "PG8" at 1646.83,2916 h25
  text "PC6" at 1944,2916 h25
  text "PB0" at 4510,2833.52 h20
  text "PC5" at 4221.83,2832.52 h25
  text "PC7" at 1646.83,2815.89 h25
  text "PC8" at 1944,2815.89 h25
  text "PC4" at 4510,2733.37 h20
  text "PA7" at 4221.83,2732.37 h25
  text "PC9" at 1646.83,2715.78 h25
  text "PA8" at 1944,2715.78 h25
  text "PA6" at 4510,2633.22 h20
  text "PA5" at 4221.83,2632.22 h25
  text "PA11" at 1634.33,2615.67 h25
  text "PA12" at 1944,2615.67 h25
  text "PA4" at 4510,2533.07 h20
  text "PA3" at 4221.83,2532.07 h25
  text "PA13" at 1626,2515.56 h25
  text "PA14" at 1944,2515.56 h25
  text "PA2" at 4510,2432.93 h20
  text "PA1" at 4230.16,2431.93 h25
  text "PA15" at 1626,2415.44 h25
  text "PC10" at 1944,2415.44 h25
  text "PA0" at 4510,2332.78 h20
  text "PC3" at 4221.83,2331.78 h25
  text "PC11" at 1634.33,2315.33 h25
  text "PC12" at 1944,2315.33 h25
  text "PC2" at 4510,2232.63 h20
  text "PC1" at 4230.16,2231.63 h25
  text "PD0" at 1646.83,2215.22 h25
  text "PD1" at 1944,2215.22 h25
  text "PC0" at 4510,2132.48 h20
  text "PF10" at 4201,2131.48 h25
  text "PD2" at 1646.83,2115.11 h25
  text "PD3" at 1944,2115.11 h25
  text "PF9" at 4510,2032.33 h20
  text "PF8" at 4221.83,2031.33 h25
  text "PD4" at 1646.83,2015 h25
  text "PD5" at 1944,2015 h25
  text "PF7" at 4510,1932.18 h20
  text "PF6" at 4221.83,1931.18 h25
  text "PD6" at 1646.83,1914.89 h25
  text "PD7" at 1944,1914.89 h25
  text "PF5" at 4510,1832.04 h20
  text "PF4" at 4221.83,1831.04 h25
  text "PG9" at 1646.83,1814.78 h25
  text "PG10" at 1944,1814.78 h25
  text "PF3" at 4510,1731.89 h20
  text "PF2" at 4221.83,1730.89 h25
  text "PG11" at 1634.33,1714.67 h25
  text "PG12" at 1944,1714.67 h25
  text "PF1" at 4510,1631.74 h20
  text "PF0" at 4221.83,1630.74 h25
  text "PG13" at 1626,1614.56 h25
  text "PG14" at 1944,1614.56 h25
  text "PC13" at 4510,1531.59 h20
  text "PE6" at 4221.83,1530.59 h25
  text "PG15" at 1626,1514.44 h25
  text "PB3" at 1944,1514.44 h25
  text "PE5" at 4510,1431.44 h20
  text "PE4" at 4221.83,1430.44 h25
  text "PB4" at 1646.83,1414.33 h25
  text "PB5" at 1944,1414.33 h25
  text "PE3" at 4510,1331.3 h20
  text "PE2" at 4221.83,1330.3 h25
  text "PB6" at 1646.83,1314.22 h25
  text "PB7" at 1944,1314.22 h25
  text "PE1" at 4510,1231.15 h20
  text "PE0" at 4221.83,1230.15 h25
  text "PB8" at 1646.83,1214.11 h25
  text "PB9" at 1944,1214.11 h25
  text "3.3" at 4510,1131 h20
  text "GND" at 4221.83,1130 h25
  text "GND" at 1646.83,1114 h25
  text "3.3" at 1944,1114 h25
  text "+12V" at 870,390 h30
  text "GND" at 1110,390 h30
  text "GND" at 4470,290 h25
  text "3.3" at 4070,280 h25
